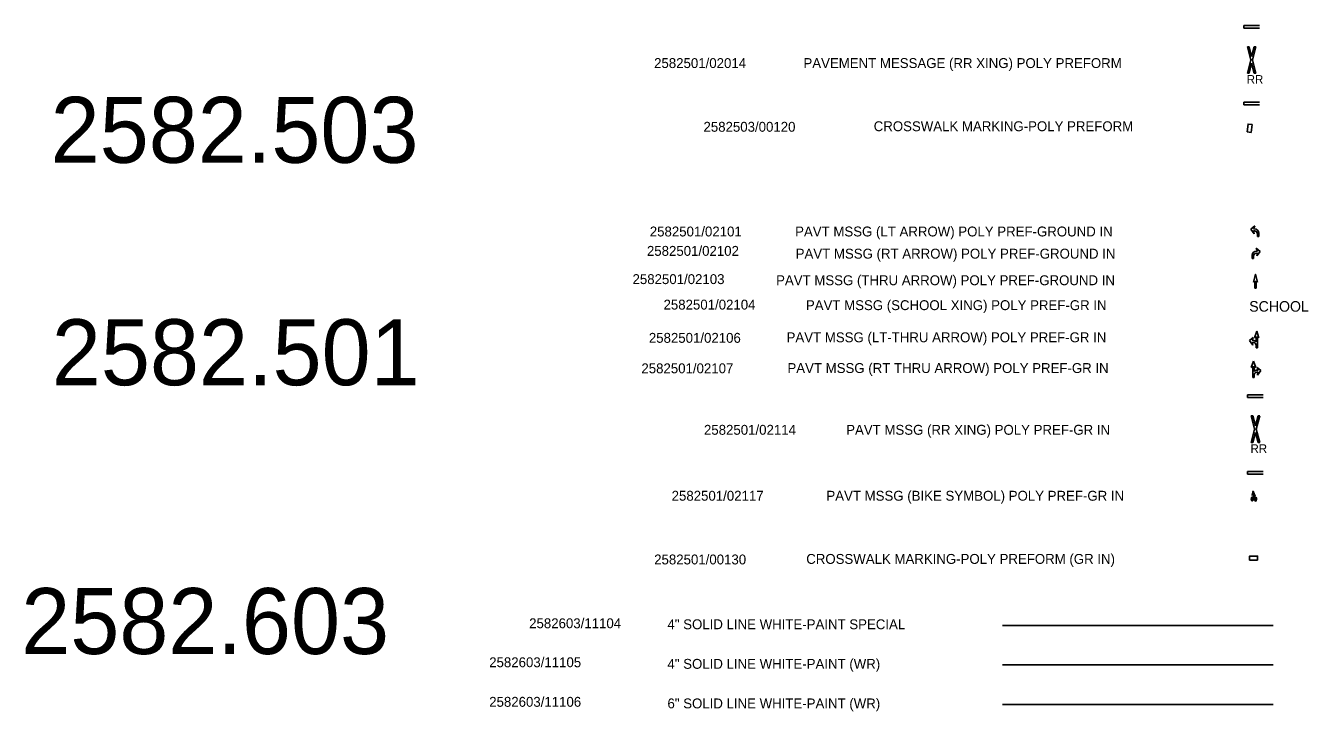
# Model space of a CAD drawing. Extents: x 2147712 to 2176316, y 2125036 to 2131746.
# Drawn here: x 2155844 to 2156817, y 2126807 to 2127327 of the extents above; entities that cross this region are included whole.
import ezdxf

# ---------------------------------------------------------------- set-up
doc = ezdxf.new("R2010")
doc.units = 0
for name, color, linetype in [('DETAIL TXT', 7, 'Continuous'), ('PVMT MARK', 7, 'Continuous'), ('PVMT STRP', 7, 'Continuous')]:
    doc.layers.add(name, color=color, linetype=linetype)

msp = doc.modelspace()

# ---------------------------------------------------------------- linework, layer by layer
at = {"layer": 'PVMT MARK'}
for p, q in [((2156767.59, 2127326.51), (2156779.59, 2127326.51)), ((2156767.59, 2127324.51), (2156767.59, 2127326.51)), ((2156779.59, 2127324.51), (2156767.59, 2127324.51)), ((2156770.39, 2127310.51), (2156772.99, 2127300.51)), ((2156772.99, 2127300.51), (2156770.39, 2127310.51)), ((2156772.99, 2127300.51), (2156770.39, 2127310.51)), ((2156770.39, 2127310.51), (2156771.69, 2127310.51)), ((2156771.69, 2127310.51), (2156773.59, 2127303.01)), ((2156773.59, 2127303.01), (2156775.59, 2127310.51)), ((2156776.89, 2127310.51), (2156774.29, 2127300.51)), ((2156775.59, 2127310.51), (2156776.89, 2127310.51)), ((2156770.39, 2127290.51), (2156772.99, 2127300.51)), ((2156773.59, 2127298.01), (2156771.69, 2127290.51)), ((2156773.59, 2127300.51), (2156773.59, 2127300.51)), ((2156775.59, 2127290.51), (2156773.59, 2127298.01)), ((2156774.29, 2127300.51), (2156776.89, 2127290.51)), ((2156771.69, 2127290.51), (2156770.39, 2127290.51)), ((2156776.89, 2127290.51), (2156775.59, 2127290.51)), ((2156767.59, 2127268.51), (2156779.59, 2127268.51)), ((2156767.59, 2127266.51), (2156767.59, 2127268.51)), ((2156779.59, 2127266.51), (2156767.59, 2127266.51)), ((2156775.96, 2127174.67), (2156772.98, 2127172.19)), ((2156772.98, 2127172.19), (2156775.46, 2127168.72)), ((2156775.05, 2127172.39), (2156775.96, 2127174.67)), ((2156775.71, 2127172.39), (2156775.05, 2127172.39)), ((2156775.46, 2127168.72), (2156775.05, 2127170.83)), ((2156775.05, 2127170.83), (2156775.71, 2127170.83)), ((2156777.94, 2127168.72), (2156777.94, 2127166.73)), ((2156777.94, 2127166.73), (2156778.93, 2127166.73)), ((2156778.93, 2127166.73), (2156778.93, 2127169.21)), ((2156774.07, 2127149.93), (2156774.07, 2127152.41)), ((2156775.07, 2127151.92), (2156775.07, 2127149.93)), ((2156777.95, 2127155.59), (2156777.05, 2127157.87)), ((2156777.05, 2127157.87), (2156780.03, 2127155.39)), ((2156777.29, 2127155.59), (2156777.95, 2127155.59)), ((2156777.95, 2127154.03), (2156777.29, 2127154.03)), ((2156780.03, 2127155.39), (2156777.55, 2127151.92)), ((2156777.55, 2127151.92), (2156777.95, 2127154.03)), ((2156775.07, 2127149.93), (2156774.07, 2127149.93)), ((2156774.88, 2127131.94), (2156776.01, 2127133.06)), ((2156776.01, 2127133.06), (2156776.01, 2127127.6)), ((2156777, 2127127.6), (2156777, 2127133.06)), ((2156777, 2127133.06), (2156778.12, 2127131.98)), ((2156776.01, 2127127.6), (2156777, 2127127.6)), ((2156775.69, 2127089.88), (2156777.42, 2127094.84)), ((2156777.42, 2127094.84), (2156779.16, 2127089.88)), ((2156771.96, 2127087.73), (2156774.71, 2127090.04)), ((2156774.44, 2127084.25), (2156771.96, 2127087.73)), ((2156774.71, 2127090.04), (2156774.05, 2127087.97)), ((2156774.05, 2127087.97), (2156774.71, 2127087.97)), ((2156774.78, 2127086.4), (2156774.11, 2127086.4)), ((2156774.11, 2127086.4), (2156774.44, 2127084.25)), ((2156776.93, 2127090.87), (2156775.69, 2127089.88)), ((2156776.93, 2127086.9), (2156776.93, 2127090.87)), ((2156776.93, 2127082.27), (2156776.93, 2127084.25)), ((2156779.16, 2127089.88), (2156777.92, 2127090.87)), ((2156777.92, 2127090.87), (2156777.92, 2127082.27)), ((2156777.92, 2127082.27), (2156776.93, 2127082.27)), ((2156775.01, 2127072.2), (2156773.27, 2127067.24)), ((2156773.27, 2127067.24), (2156774.51, 2127068.24)), ((2156774.51, 2127068.24), (2156774.51, 2127059.64)), ((2156776.74, 2127067.24), (2156775.01, 2127072.2)), ((2156775.5, 2127064.27), (2156775.5, 2127068.24)), ((2156775.5, 2127068.24), (2156776.74, 2127067.24)), ((2156777.65, 2127063.77), (2156778.31, 2127063.77)), ((2156780.46, 2127065.09), (2156777.72, 2127067.41)), ((2156777.72, 2127067.41), (2156778.38, 2127065.34)), ((2156778.38, 2127065.34), (2156777.72, 2127065.34)), ((2156777.98, 2127061.62), (2156780.46, 2127065.09)), ((2156778.31, 2127063.77), (2156777.98, 2127061.62)), ((2156774.51, 2127059.64), (2156775.5, 2127059.64)), ((2156775.5, 2127059.64), (2156775.5, 2127061.62)), ((2156770.44, 2127046.58), (2156782.44, 2127046.58)), ((2156770.44, 2127044.58), (2156770.44, 2127046.58)), ((2156782.44, 2127044.58), (2156770.44, 2127044.58)), ((2156773.24, 2127030.58), (2156775.84, 2127020.58)), ((2156775.84, 2127020.58), (2156773.24, 2127030.58)), ((2156775.84, 2127020.58), (2156773.24, 2127030.58)), ((2156773.24, 2127030.58), (2156774.54, 2127030.58)), ((2156774.54, 2127030.58), (2156776.44, 2127023.08)), ((2156776.44, 2127023.08), (2156778.44, 2127030.58)), ((2156779.74, 2127030.58), (2156777.14, 2127020.58)), ((2156778.44, 2127030.58), (2156779.74, 2127030.58)), ((2156773.24, 2127010.58), (2156775.84, 2127020.58)), ((2156776.44, 2127018.08), (2156774.54, 2127010.58)), ((2156776.44, 2127020.58), (2156776.44, 2127020.58)), ((2156778.44, 2127010.58), (2156776.44, 2127018.08)), ((2156777.14, 2127020.58), (2156779.74, 2127010.58)), ((2156774.54, 2127010.58), (2156773.24, 2127010.58)), ((2156779.74, 2127010.58), (2156778.44, 2127010.58)), ((2156770.44, 2126988.58), (2156782.44, 2126988.58)), ((2156770.44, 2126986.58), (2156770.44, 2126988.58)), ((2156782.44, 2126986.58), (2156770.44, 2126986.58)), ((2156773.5, 2126968.57), (2156773.5, 2126968.67)), ((2156774.6, 2126972.37), (2156774.1, 2126970.87)), ((2156774.1, 2126970.87), (2156774.3, 2126970.27)), ((2156774.26, 2126973.16), (2156774.41, 2126973.17)), ((2156774.3, 2126970.27), (2156774.8, 2126971.67)), ((2156775.5, 2126970.37), (2156774.4, 2126969.67)), ((2156774.4, 2126969.67), (2156775.1, 2126968.77)), ((2156775.1, 2126972.87), (2156774.6, 2126972.37)), ((2156774.8, 2126971.67), (2156775.5, 2126970.37)), ((2156774.88, 2126973.17), (2156775.02, 2126973.16)), ((2156776.3, 2126969.87), (2156775.1, 2126972.87)), ((2156775.1, 2126969.47), (2156775.7, 2126969.97)), ((2156775.3, 2126969.07), (2156775.1, 2126969.47)), ((2156775.1, 2126968.77), (2156775.3, 2126969.07)), ((2156775.7, 2126969.97), (2156775.2, 2126967.77)), ((2156775.2, 2126967.77), (2156775.3, 2126967.07)), ((2156775.3, 2126967.17), (2156776.3, 2126969.87)), ((2156776, 2126966.77), (2156776.5, 2126966.87))]:
    msp.add_line(p, q, dxfattribs=at)
for points in [[(2156770.19, 2127245.95), (2156773.17, 2127245.57), (2156773.92, 2127251.53), (2156770.94, 2127251.9)], [(2156778.07, 2126921.31), (2156778.07, 2126924.31), (2156772.07, 2126924.31), (2156772.07, 2126921.31)]]:
    msp.add_lwpolyline(points, close=True, dxfattribs=at)
msp.add_lwpolyline([(2156778.12, 2127131.98), (2156776.5, 2127138.07), (2156774.88, 2127131.98)], dxfattribs=at)
for centre, radius in [((2156773.58, 2127300.51), 0.04), ((2156773.58, 2127300.51), 0.035), ((2156776.44, 2127020.58), 0.04), ((2156776.44, 2127020.58), 0.035)]:
    msp.add_circle(centre, radius, dxfattribs=at)
for centre, radius, start, end in [((2156775.71, 2127169.16), 3.22, 0.85489, 89.91229), ((2156775.79, 2127168.69), 2.15, 0.74176, 90.20562), ((2156777.3, 2127152.36), 3.22, 90.08771, 179.14511), ((2156777.21, 2127151.89), 2.15, 89.79438, 179.25824), ((2156774.52, 2127084.76), 3.22, 41.67105, 86.55067), ((2156774.78, 2127084.25), 2.15, 0, 90), ((2156777.91, 2127062.12), 3.22, 93.44933, 138.32895), ((2156777.65, 2127061.62), 2.15, 90, 180), ((2156774.64, 2126973.16), 0.38, 0, 180), ((2156774.64, 2126973.17), 0.233, 179.88048, 0.11957)]:
    msp.add_arc(centre, radius, start, end, dxfattribs=at)
for centre, major_axis, ratio, start_param, end_param in [((2156774.03, 2126967.58), (0.02, -1.55), 0.456256, 3.992611, 7.057282), ((2156774.03, 2126967.58), (0.02, -1.55), 0.456256, 0.776758, 3.974471), ((2156774.03, 2126967.57), (0.01, -1.05), 0.197843, 4.125672, 6.670705), ((2156774.03, 2126967.57), (0.01, -1.05), 0.197843, 0.431648, 4.124808), ((2156776.59, 2126967.57), (0.02, -1.55), 0.456256, 5.23952, 11.521386), ((2156776.59, 2126967.57), (0.01, -1.05), 0.197843, 5.45221, 11.728621)]:
    msp.add_ellipse(centre, major_axis=major_axis, ratio=ratio, start_param=start_param, end_param=end_param, dxfattribs=at)
at = {"layer": 'PVMT STRP'}
for p, q in [((2156584.75, 2126871.81), (2156789.95, 2126871.81)), ((2156584.75, 2126841.81), (2156789.95, 2126841.81)), ((2156584.75, 2126811.81), (2156789.95, 2126811.81))]:
    msp.add_line(p, q, dxfattribs=at)

# ---------------------------------------------------------------- texts
at = {"layer": 'DETAIL TXT'}
for s, height, p in [('2582501/02014', 7.5, (2156320.62, 2127294.37)), ('PAVEMENT MESSAGE (RR XING) POLY PREFORM', 7.5, (2156433.83, 2127294.37)), ('2582.503', 50, (2155863.16, 2127222.52)), ('2582503/00120', 7.5, (2156358.05, 2127246.07)), ('CROSSWALK MARKING-POLY PREFORM', 7.5, (2156487.11, 2127246.49)), ('2582501/02101', 7.5, (2156317.34, 2127166.69)), ('PAVT MSSG (LT ARROW) POLY PREF-GROUND IN', 7.5, (2156427.53, 2127166.69)), ('2582501/02102', 7.5, (2156315.18, 2127151.99)), ('PAVT MSSG (RT ARROW) POLY PREF-GROUND IN', 7.5, (2156427.95, 2127149.89)), ('2582501/02103', 7.5, (2156304.26, 2127130.57)), ('PAVT MSSG (THRU ARROW) POLY PREF-GROUND IN', 7.5, (2156413.1, 2127129.73)), ('2582501/02104', 7.5, (2156327.76, 2127111.25)), ('PAVT MSSG (SCHOOL XING) POLY PREF-GR IN', 7.5, (2156435.69, 2127110.83)), ('2582.501', 50, (2155864.06, 2127053.88)), ('2582501/02106', 7.5, (2156316.64, 2127086.05)), ('PAVT MSSG (LT-THRU ARROW) POLY PREF-GR IN', 7.5, (2156421.05, 2127086.47)), ('2582501/02107', 7.5, (2156310.98, 2127062.95)), ('PAVT MSSG (RT THRU ARROW) POLY PREF-GR IN', 7.5, (2156421.68, 2127063.16)), ('2582501/02114', 7.5, (2156358.42, 2127016.33)), ('PAVT MSSG (RR XING) POLY PREF-GR IN', 7.5, (2156466.23, 2127016.33)), ('2582501/02117', 7.5, (2156333.91, 2126966.33)), ('PAVT MSSG (BIKE SYMBOL) POLY PREF-GR IN', 7.5, (2156451.23, 2126966.33)), ('2582501/00130', 7.5, (2156320.67, 2126918.03)), ('CROSSWALK MARKING-POLY PREFORM (GR IN)', 7.5, (2156435.94, 2126918.45)), ('2582.603', 50, (2155840.85, 2126850.1)), ('2582603/11104', 7.5, (2156225.9, 2126869.65)), ('4" SOLID LINE WHITE-PAINT SPECIAL', 7.5, (2156330.75, 2126868.89)), ('2582603/11105', 7.5, (2156195.61, 2126840.09)), ('4" SOLID LINE WHITE-PAINT (WR)', 7.5, (2156330.75, 2126838.89)), ('2582603/11106', 7.5, (2156195.61, 2126810.09)), ('6" SOLID LINE WHITE-PAINT (WR)', 7.5, (2156330.75, 2126808.89))]:
    msp.add_text(s, height=height, dxfattribs=at).set_placement(p)
at = {"layer": 'PVMT MARK'}
for s, height, p in [('RR', 6.5, (2156769.89, 2127282.51)), ("AREA = 15 SQ'", 0.0992, (2156775.76, 2127171.76)), ("REM = 48 SQ '", 0.0992, (2156775.82, 2127171.43)), ("PERIMETER = 30 '", 0.0992, (2156775.84, 2127171.11)), ('PERIMETER 30 FT', 0.0907, (2156775.75, 2127133.7)), ('REM 35 SF', 0.0907, (2156775.99, 2127134.05)), ('AREA 15 SF', 0.0907, (2156776.08, 2127134.34)), ('SCHOOL', 8, (2156771.75, 2127109.66)), ('AREA 26 SQ FT', 0.0992, (2156773.2, 2127087.55)), ('REM 95 SQ FT', 0.0992, (2156773.23, 2127087.34)), ('PERIMETER 50FT', 0.0992, (2156773.26, 2127087.1)), ('RR', 6.5, (2156772.74, 2127002.58))]:
    msp.add_text(s, height=height, dxfattribs=at).set_placement(p)
for s, p in [("PERIMETER = 30 '", (2156775.82, 2127154.23)), ("REM = 48 SQ '", (2156776.08, 2127154.56)), ("AREA = 15 SQ'", (2156776.18, 2127154.88)), ('PERIMETER 50FT', (2156777.92, 2127064.46)), ('AREA 26 SQ FT', (2156778.03, 2127064.92)), ('REM 95 SQ FT', (2156778.09, 2127064.71))]:
    msp.add_text(s, height=0.0992, rotation=360, dxfattribs=at).set_placement(p)

doc.saveas('drawing.dxf')
